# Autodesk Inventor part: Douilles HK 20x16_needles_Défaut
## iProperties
Shininess: 64.0
Length Units: 11269
Angle Units: 11279
Time Units: 11290
Mass Units: 11283
Length Display Precision: 3
Angle Display Precision: 2
Compacted: True
Part Number: Douilles HK 20x16_needles_Défaut
Document SubType Name: Modeling
Created: 2006-01
Material: Par défaut
Designer: riri
Density: 0.0
Volumn: 0.0
Area: 0.0
PropertySet Name: Model Information
Control State: 0
Master: False
Checked Out: False
Author: riri
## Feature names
1. Base1
